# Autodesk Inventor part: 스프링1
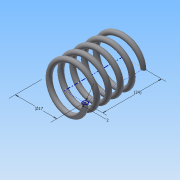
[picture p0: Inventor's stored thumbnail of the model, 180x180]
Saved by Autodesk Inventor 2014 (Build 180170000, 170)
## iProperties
Created: 2016-01
Part Number: 스프링1
Material: 강철, 탄소
Document SubType Name: Modeling
Designer: Administrator
Density: 1 g/cm^3
Appearance: 반연마
Mass: 0.821961 g
Surface Area: 16.7185 cm^2
Volume: 0.821961 cm^3
Author: Administrator
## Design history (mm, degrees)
sketch "스케치1"
  geometry: L1 (0, 0)-(8.5, 0); L2 (8.5, 0)-(8.5, 20.5); L3 (8.5, 20.5)-(0, 20.5); L4 (0, 20.5)-(0, 0); C1 r 1 at (8.5, 0)
  constraints: 8 end point, 2 parallel, 1 centre point, 1 coincident, 1 horizontal, 1 perpendicular
  dimensions: "d0" = 20.5 distance of L1.end L2.end (derived); "d1" = 2 diameter of C1; "d2" = 17 diameter of L2 L4
feature "코일1" sketch "스케치1" pitch "d3" = 10; turns "d5" = 5; dims "d4" = 20.5 (= d0), "d6" = 0, angle "d7" = 90 deg, angle "d8" = 90 deg, "d9" = 0, "d10" = 0
node "작업 평면1"
sketch "스케치2"
  geometry: L1 (7.5, 0)-(9.5, 0) reference; 1 further point
  constraints: 1 horizontal alignment
extrude "돌출1" cut sketch "스케치2" distance "d12" = 10; taper "d13" = 0 deg
node "작업 평면2"
sketch "스케치3"
  geometry: L1 (-7.5, 0)-(-9.5, 0) reference; 1 further point
  constraints: 1 horizontal alignment
extrude "돌출2" cut sketch "스케치3" distance "d15" = 10; taper "d16" = 0 deg
node "솔리드1"
node "절단 모서리 투영1"
node "절단 모서리 투영2"
other parameters: "d11" = 0, "d14" = -20.5 (= -d0)
